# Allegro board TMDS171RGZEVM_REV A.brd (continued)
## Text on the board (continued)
PAGE_OUTLINE: GENERAL NOTES. UNLESS OTHERWISE SPECIFIED | 1.  ALL FABRICATION ITEMS MUST MEET OR EXCEED BEST | INDUSTRY PRACTICE : IPC-A-600C (Commercial std.) | 2.  LAMINATE MATERIAL  :  FR4 POLYCLAD 370 or EQUIVALENT | 3.  COPPER WEIGHT  : 1oz START INTERNAL, 1/2oz START EXTERNAL | 4.  FINISHED BOARD THICKNESS :  .062  +/- 10% | 5.  MAXIMUM WARP AND TWIST TO BE :  .005 INCH PER INCH | 6.  MINIMUM COPPER WALL THICKNESS OF PLATED-THRU | HOLES TO BE .001 INCH. THERE MUST BE 1MIL OR GREATER PLATING ON | EACH SIDE OF THE BARREL WHEN VIEWED IN THE CROSS SECTION | 7.  MINIMUM ANNULAR RING OF PLATED-THRU HOLES | TO BE .002 INCH | 8.  MAXIMUM ALLOWABLE LINE REDUCTION TO BE | 20% OR .002 WHICHEVER IS SMALLER | 9.  0.005 SIGNAL LINES ON LAYER 1 & 6 TO BE | IMPEDANCE CONTROLLED 100 OHMS DIFFERENTIAL +/- 5% | 10. 0.008 SIGNAL LINES ON LAYER 1 & 6 TO BE | IMPEDANCE CONTROLLED 50 OHMS +/- 5% | 11. DIELECTRIC CONSTANTS ARE         CORE : 4.1 | PREPREG : 4.1 | 13. A CROSS SECTION MOUNT AND DIGITAL PHOTO'S OF VIA'S TO BE PROVIDED | PROCESS NOTES | 1. CIRCUITRY ON OUTER LAYERS TO BE PLATED WITH : NICKEL GOLD | 2. SOLDERMASK BOTH SIDES PER ARTWORK  :  GREEN LPI | 3. SILKSCREEN BOTH SIDES PER ARTWORK  :  COLOR = WHITE | LAYER 13 - FAB
DISPLAY_TOP: 20mil | 5mil | 1 | 2 | 3 | 4 | 5 | 6 | TOP | L2 | L3 | L4 | L5 | BOTTOM
User.9: FIGURE | SIZE | 160.0 | 140.0 | 120.0 | 98.0 | 90.55 | 73.0 | 52.0 | 40.0 | 39.0 | 38.0 | 12.0 | 8.0 | 41.34 | 106.3x35.43 | 66.93x35.43 | 51.18x27.56 | 41.34x25.59 | DRILL CHART: TOP to BOTTOM | ALL UNITS ARE IN MILS | TOLERANCE | +3.0/-3.0 | +2.0/-2.0 | +3.0/-12.0 | +1.97/-1.97 | +3.15/-3.15 | PLATED | NON-PLATED | QTY | 4 | 1 | 2 | 3 | 17 | 10 | 33 | 12 | 262
